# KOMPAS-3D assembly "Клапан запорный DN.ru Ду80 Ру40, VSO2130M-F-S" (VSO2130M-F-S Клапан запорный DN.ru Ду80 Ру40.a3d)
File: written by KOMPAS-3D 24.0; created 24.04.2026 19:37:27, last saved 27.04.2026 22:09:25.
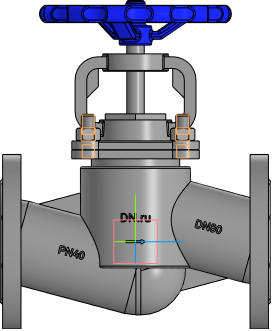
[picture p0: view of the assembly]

Document properties: Автор: DN.ru; Полное имя файла: C:\Работа\ГОТОВЫЕ ИСХОДНИКИ\VSO2130M-F-S Клапан запорный сальниковый DN.ru Ду15-100 Ру40\исходные материалы\DN80\VSO2130M-F-S Клапан запорный DN.ru Ду80 Ру40.a3d

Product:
- Component [detail]: Корпус  | qty 1  | pos. 1  | Масса: 6.9; Автор: R2D2; source file: Korpus.m3d
- Component [detail]: Деталь  | qty 1  | pos. 2  | Масса: 4.585607; Автор: mrdid; source file: rama.m3d
- Component [detail]: Деталь2  | qty 1  | pos. 3  | Масса: 2.292394; Автор: R2D2; additional columns: Типовые; source file: shturval.m3d
- Component [standard]: Шпилька М16-6gx35 ГОСТ 22032-76  | qty 4  | Масса: 0.07017; Раздел спецификации: Стандартные изделия; Рассекать на разрезах: no
- Component [standard]: Гайка М16-6H ГОСТ 5915-70  | qty 4  | Масса: 0.03761; Раздел спецификации: Стандартные изделия; Рассекать на разрезах: no
- Part/product: Клапан запорный DN.ru Ду80 Ру40  | designation VSO2130M-F-S
    Масса: 30
    Раздел спецификации: Прочие изделия
    Примечание: D090-01986

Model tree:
1. Контекстная связь:1  (with: Контекстная связь (Деталь):1)  (labels: Грань.Твердое тело1)
2. Контекстная связь:2  (with: Смещенная плоскость:4, Контекстная связь (Деталь):2, Грань.Элемент выдавливания:1, Грань.Элемент выдавливания:15, Грань.Элемент выдавливания:3, Грань.Элемент выдавливания:14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)  (labels: Грань.Твердое тело1; Грань.Элемент выдавливания:16.Экземпляр ( 2, 2 ); Грань.Элемент выдавливания:2.Экземпляр ( 2, 2 ); Грань.Элемент выдавливания:16.Экземпляр ( 2, 1 ))
     Угол = 9

Referenced files in C:\Работа\ГОТОВЫЕ ИСХОДНИКИ\VSO2130M-F-S Клапан запорный сальниковый DN.ru Ду15-100 Ру40\исходные материалы\DN80\: Korpus.m3d, rama.m3d, shturval.m3d, 
Referenced files in C:\Program Files\ASCON\KOMPAS-3D v24\Libs\Pipeline\: StylesTemplate.a3d, TemplateHPH, InsulationStylesTemplate.a3d, Insulation
Referenced files in C:\Program Files\ASCON\KOMPAS-3D v24\Templates\: Констр. чертеж А3 гориз. перв. лист.cdt
Referenced files in C:\Program Files\ASCON\KOMPAS-3D v24\Libs\PolynomLib\DATA\vault\Methods\Kompas\3D\: PLib_Stud_1_900.m3d, PLib_Nut_OST92_900.m3d
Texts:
  Крепежное изделие ГОСТ
  BOSimple***PART:d7cea355-acbb-e7a9-246f-9517ee95b2f8***SHORTLOC:Root±30±20±10±120±10±20[Нет;Без покрытия;Без указания материала;-;16;35;2;2]
  BOSimple***PART:17b45fe1-43c8-f41a-5df4-ae57481e6c3b***SHORTLOC:Root±30±10±20±©{}110±10±50±60[Нет;Без покрытия;Без указания материала;-;16;2;24]
  Программные изделия  и базы данных
  VSO2130M-F-S
  Отводы ГОСТ 17375-2001
  Констр. чертеж А3 гориз. перв. лист.cdt
  Деталь2 Деталь2
  Шпилька М16-6gx35 ГОСТ 22032-76 (1)
  cut1
  Шпилька М16-6gx35 ГОСТ 22032-76 (2)
  Шпилька М16-6gx35 ГОСТ 22032-76 (4)
  Шпилька М16-6gx35 ГОСТ 22032-76 (6)
  Гайка М16-6H ГОСТ 5915-70 (1)
  bcut1
  hole1
  hcut1
  hole2
  Гайка М16-6H ГОСТ 5915-70 (2)
  Гайка М16-6H ГОСТ 5915-70 (4)
  Гайка М16-6H ГОСТ 5915-70 (6)
  Плоскость ZX.Начало координат
  Плоскость XY.Начало координат
  Грань.Элемент выдавливания:16.Экземпляр ( 1, 2 )
  Plane. Начало координат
